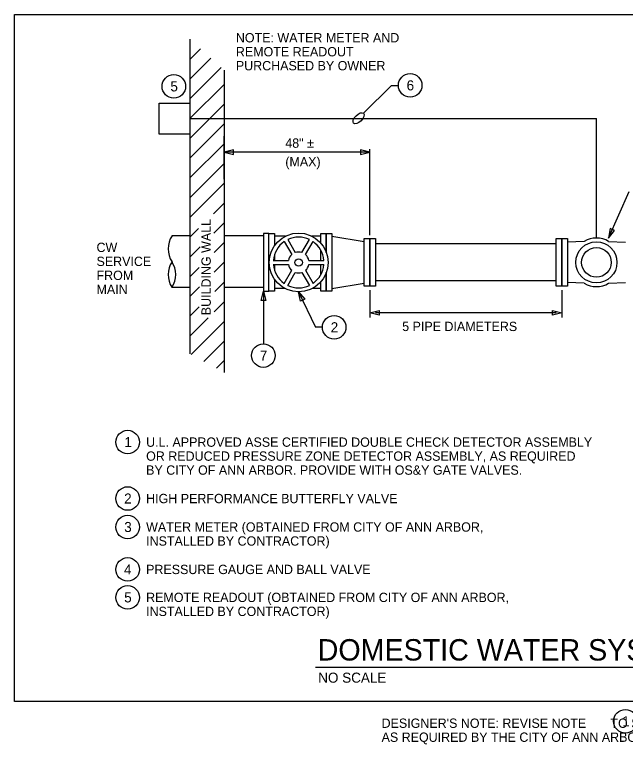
# Model space of a CAD drawing. Extents: x 10291.2 to 10382.2, y 10083.1 to 10135.3.
# Drawn here: x 10291.2 to 10334.8, y 10083.1 to 10135.3 of the extents above; entities that cross this region are included whole.
import ezdxf

# ---------------------------------------------------------------- set-up
doc = ezdxf.new("R2010")
doc.units = 0
for name, color, linetype in [('G-ANNO-CELL', 7, 'Continuous'), ('G-ANNO-NPLT', 7, 'Continuous'), ('G-ANNO-SYMB', 7, 'Continuous'), ('G-DETL-LINE', 7, 'Continuous'), ('G-DETL-TEXT', 7, 'Continuous')]:
    doc.layers.add(name, color=color, linetype=linetype)

msp = doc.modelspace()

# ---------------------------------------------------------------- linework, layer by layer
at = {"layer": 'G-ANNO-CELL'}
msp.add_line((10312.677, 10088.609), (10360.636, 10088.609), dxfattribs=at)
at = {"layer": 'G-ANNO-NPLT'}
msp.add_lwpolyline([(10291.157, 10086.15), (10291.157, 10135.292), (10336.657, 10135.292), (10336.657, 10086.15)], close=True, dxfattribs=at)
at = {"layer": 'G-ANNO-SYMB'}
for centre in [(10319.449, 10130.229), (10302.544, 10130.155), (10314.015, 10112.921), (10308.95, 10110.897), (10299.241, 10104.704), (10299.241, 10100.667), (10299.241, 10098.63), (10299.241, 10095.594), (10299.241, 10093.594), (10334.844, 10084.732)]:
    msp.add_circle(centre, 0.843, dxfattribs=at)
at = {"layer": 'G-DETL-LINE'}
for p, q in [((10303.692, 10133.537), (10303.692, 10111.026)), ((10303.692, 10132.091), (10304.451, 10132.849)), ((10303.692, 10130.676), (10305.193, 10132.177)), ((10303.692, 10129.262), (10305.935, 10131.505)), ((10306.141, 10131.319), (10306.141, 10109.695)), ((10303.692, 10127.848), (10306.141, 10130.296)), ((10303.692, 10126.434), (10306.141, 10128.882)), ((10303.692, 10127.848), (10332.768, 10127.848)), ((10303.692, 10125.02), (10306.141, 10127.468)), ((10332.768, 10119.303), (10332.768, 10127.848)), ((10303.692, 10123.605), (10306.141, 10126.054)), ((10303.692, 10122.191), (10306.141, 10124.639)), ((10303.692, 10120.777), (10306.141, 10123.225)), ((10305.378, 10121.048), (10306.141, 10121.811)), ((10305.399, 10119.655), (10306.141, 10120.397)), ((10303.692, 10119.363), (10304.316, 10119.986)), ((10303.712, 10119.454), (10302.414, 10119.454)), ((10308.95, 10119.454), (10306.141, 10119.454)), ((10310.526, 10119.436), (10309.751, 10119.436)), ((10310.692, 10119.201), (10311.233, 10118.264)), ((10311.711, 10118.264), (10312.253, 10119.201)), ((10313.049, 10119.436), (10312.419, 10119.436)), ((10313.838, 10119.436), (10316.157, 10119.066)), ((10331.891, 10119.066), (10330.692, 10119)), ((10333.644, 10119.066), (10334.843, 10119)), ((10303.692, 10117.948), (10304.427, 10118.683)), ((10305.421, 10118.262), (10306.141, 10118.983)), ((10310.438, 10119.054), (10310.98, 10118.117)), ((10311.965, 10118.117), (10312.506, 10119.054)), ((10329.891, 10118.9), (10316.958, 10118.9)), ((10305.431, 10116.859), (10306.141, 10117.568)), ((10309.658, 10117.706), (10310.741, 10117.706)), ((10312.204, 10117.706), (10313.286, 10117.706)), ((10303.692, 10116.534), (10304.361, 10117.203)), ((10309.658, 10117.407), (10310.741, 10117.407)), ((10310.438, 10116.059), (10310.98, 10116.996)), ((10311.965, 10116.996), (10312.506, 10116.059)), ((10312.204, 10117.407), (10313.286, 10117.407)), ((10310.692, 10115.912), (10311.233, 10116.849)), ((10311.711, 10116.849), (10312.253, 10115.912)), ((10305.472, 10115.486), (10306.141, 10116.154)), ((10313.838, 10115.696), (10316.157, 10116.066)), ((10329.891, 10116.233), (10316.958, 10116.233)), ((10331.891, 10116.066), (10330.692, 10116.132)), ((10333.644, 10116.066), (10334.843, 10116.132)), ((10303.712, 10115.761), (10302.414, 10115.761)), ((10303.692, 10115.12), (10304.387, 10115.815)), ((10308.95, 10115.761), (10306.141, 10115.761)), ((10310.488, 10115.696), (10309.751, 10115.696)), ((10313.049, 10115.696), (10312.456, 10115.696)), ((10303.692, 10113.706), (10304.363, 10114.376)), ((10305.433, 10114.032), (10306.141, 10114.74)), ((10303.692, 10112.292), (10304.999, 10113.598)), ((10303.788, 10110.973), (10306.141, 10113.326)), ((10304.691, 10110.483), (10306.141, 10111.933)), ((10305.586, 10109.996), (10306.141, 10110.551))]:
    msp.add_line(p, q, dxfattribs=at)
for points in [[(10301.49, 10128.949), (10303.692, 10128.949), (10303.692, 10126.747), (10301.49, 10126.747)], [(10316.157, 10119.269), (10316.558, 10119.269), (10316.558, 10115.864), (10316.157, 10115.864)], [(10316.558, 10119.269), (10316.958, 10119.269), (10316.958, 10115.864), (10316.558, 10115.864)], [(10329.891, 10119.269), (10330.292, 10119.269), (10330.292, 10115.864), (10329.891, 10115.864)], [(10330.292, 10119.269), (10330.692, 10119.269), (10330.692, 10115.864), (10330.292, 10115.864)]]:
    msp.add_lwpolyline(points, close=True, dxfattribs=at)
for points in [[(10309.35, 10118.277), (10309.35, 10119.639), (10308.95, 10119.639), (10308.95, 10115.494), (10309.35, 10115.494), (10309.35, 10116.836)], [(10309.751, 10116.346), (10309.751, 10115.494), (10309.35, 10115.494), (10309.35, 10119.639), (10309.751, 10119.639), (10309.751, 10118.767)], [(10313.049, 10118.951), (10313.049, 10119.639), (10313.45, 10119.639), (10313.45, 10118.277)], [(10313.45, 10118.277), (10313.45, 10119.639), (10313.85, 10119.639), (10313.85, 10115.494), (10313.45, 10115.494), (10313.45, 10116.836)], [(10309.751, 10118.129), (10309.751, 10117.706)], [(10313.049, 10117.706), (10313.049, 10118.453)], [(10309.751, 10117.407), (10309.751, 10116.984)], [(10313.049, 10116.66), (10313.049, 10117.407)], [(10313.45, 10116.836), (10313.45, 10115.494), (10313.049, 10115.494), (10313.049, 10116.162)]]:
    msp.add_lwpolyline(points, dxfattribs=at)
for centre, radius in [((10311.472, 10117.557), 2.105), ((10332.768, 10117.566), 1.472), ((10332.768, 10117.566), 1.062), ((10311.472, 10117.557), 0.265)]:
    msp.add_circle(centre, radius, dxfattribs=at)
for centre, radius, start, end in [((10303.833, 10118.533), 1.691, 147.0136, 212.9864), ((10311.472, 10117.557), 1.814, 64.6295, 115.3705), ((10332.768, 10117.566), 1.737, 59.7065, 120.2935), ((10311.472, 10117.557), 1.814, 124.6295, 175.2858), ((10311.472, 10117.557), 1.814, 4.7142, 55.3705), ((10311.472, 10117.557), 0.746, 131.3127, 168.4779), ((10311.472, 10117.557), 0.746, 71.3127, 108.6873), ((10311.472, 10117.557), 0.746, 11.5221, 48.6873), ((10303.833, 10116.691), 1.691, 147.0136, 212.9864), ((10300.996, 10116.691), 1.691, 327.0136, 32.9864), ((10311.472, 10117.557), 1.814, 184.7142, 235.3705), ((10311.472, 10117.557), 0.746, 191.5221, 228.6873), ((10311.472, 10117.557), 0.746, 311.3127, 348.4779), ((10311.472, 10117.557), 1.814, 304.6295, 355.2858), ((10311.472, 10117.557), 0.746, 251.3127, 288.6873), ((10332.768, 10117.566), 1.737, 239.7065, 300.2935), ((10311.472, 10117.557), 1.814, 244.6295, 295.3705)]:
    msp.add_arc(centre, radius, start, end, dxfattribs=at)
at = {"layer": 'G-DETL-TEXT'}
for p, q in [((10318.107, 10130.229), (10316.11, 10128.232)), ((10318.107, 10130.229), (10318.607, 10130.229)), ((10306.141, 10123.514), (10306.141, 10126.591)), ((10306.141, 10126.38), (10306.141, 10126.38)), ((10307.839, 10125.442), (10306.141, 10125.442)), ((10316.558, 10125.442), (10307.839, 10125.442)), ((10316.558, 10119.508), (10316.558, 10125.653)), ((10333.644, 10119.305), (10335.107, 10122.629)), ((10308.95, 10115.494), (10308.95, 10111.74)), ((10311.472, 10115.452), (10312.672, 10112.921)), ((10316.558, 10115.564), (10316.558, 10113.615)), ((10330.292, 10115.564), (10330.292, 10113.615)), ((10329.891, 10113.948), (10316.958, 10113.948)), ((10313.172, 10112.921), (10312.672, 10112.921))]:
    msp.add_line(p, q, dxfattribs=at)
for points in [[(10306.807, 10125.608), (10306.141, 10125.442), (10306.807, 10125.275)], [(10315.891, 10125.275), (10316.558, 10125.442), (10315.891, 10125.608)], [(10333.76, 10119.983), (10333.644, 10119.305), (10334.065, 10119.848)], [(10308.783, 10114.827), (10308.95, 10115.494), (10309.116, 10114.827)], [(10311.607, 10114.778), (10311.472, 10115.452), (10311.909, 10114.921)], [(10317.225, 10113.781), (10316.558, 10113.948), (10317.225, 10114.115)], [(10329.625, 10114.115), (10330.292, 10113.948), (10329.625, 10113.781)]]:
    msp.add_lwpolyline(points, close=True, dxfattribs=at)
msp.add_ellipse((10315.756, 10127.878), major_axis=(-0.354, -0.354), ratio=0.5, dxfattribs=at)

# ---------------------------------------------------------------- texts
at = {"layer": 'G-ANNO-CELL'}
for s, height, p in [('DOMESTIC WATER SYSTEM SERVICE DETAIL', 1.53173, (10312.834, 10089.076)), ('NO SCALE', 0.7208, (10312.873, 10087.49))]:
    msp.add_text(s, height=height, dxfattribs=at).set_placement(p)
at = {"layer": 'G-ANNO-SYMB'}
for s, p in [('6', (10319.195, 10129.868)), ('5', (10302.3, 10129.795)), ('2', (10313.766, 10112.561)), ('7', (10308.697, 10110.537)), ('1', (10299.01, 10104.343)), ('2', (10298.992, 10100.307)), ('3', (10298.998, 10098.27)), ('4', (10298.983, 10095.234)), ('5', (10298.996, 10093.234)), ('1', (10334.613, 10084.372))]:
    msp.add_text(s, height=0.721, dxfattribs=at).set_placement(p)
at = {"layer": 'G-DETL-TEXT'}
for s, height, p in [('NOTE: WATER METER AND', 0.66667, (10306.982, 10133.303)), ('REMOTE READOUT', 0.66667, (10306.982, 10132.303)), ('PURCHASED BY OWNER', 0.66667, (10306.982, 10131.303)), ('48" ±', 0.6667, (10310.519, 10125.766)), ('(MAX)', 0.6667, (10310.519, 10124.433)), ('CW', 0.6667, (10297.015, 10118.304)), ('SERVICE', 0.6667, (10297.015, 10117.304)), ('FROM', 0.6667, (10297.015, 10116.304)), ('MAIN', 0.6667, (10297.015, 10115.304)), ('5 PIPE DIAMETERS', 0.66667, (10318.879, 10112.65)), ('U.L. APPROVED ASSE CERTIFIED DOUBLE CHECK DETECTOR ASSEMBLY', 0.66667, (10300.564, 10104.37)), ('OR REDUCED PRESSURE ZONE DETECTOR ASSEMBLY, AS REQUIRED', 0.66667, (10300.564, 10103.37)), ('BY CITY OF ANN ARBOR. PROVIDE WITH OS&Y GATE VALVES.', 0.66667, (10300.564, 10102.37)), ('HIGH PERFORMANCE BUTTERFLY VALVE', 0.66667, (10300.564, 10100.334)), ('WATER METER (OBTAINED FROM CITY OF ANN ARBOR,', 0.66667, (10300.564, 10098.297)), ('INSTALLED BY CONTRACTOR)', 0.66667, (10300.564, 10097.297)), ('PRESSURE GAUGE AND BALL VALVE', 0.66667, (10300.564, 10095.261)), ('REMOTE READOUT (OBTAINED FROM CITY OF ANN ARBOR,', 0.66667, (10300.564, 10093.261)), ('INSTALLED BY CONTRACTOR)', 0.66667, (10300.564, 10092.261)), ("DESIGNER'S NOTE: REVISE NOTE       TO SPECIFY A RPZ OR A DOUBLE CHECK ASSEMBLY,", 0.66667, (10317.404, 10084.259)), ('AS REQUIRED BY THE CITY OF ANN ARBOR BASED ON THE BUILDING HAZARD LEVEL.', 0.66667, (10317.404, 10083.259))]:
    msp.add_text(s, height=height, dxfattribs=at).set_placement(p)
msp.add_text('BUILDING WALL', height=0.66667, rotation=90, dxfattribs=at).set_placement((10305.188, 10113.783))

doc.saveas('drawing.dxf')
